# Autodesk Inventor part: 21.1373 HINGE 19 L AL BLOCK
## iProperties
Created: 2007-01
Part Number: 21.1373 HINGE 19 L AL BLOCK
Document SubType Name: Modeling
Designer: Andy Moles
Material: Aluminum-6061
Density: 2.71 g/cm^3
Mass: 18.3877 g
Surface Area: 42.4483 cm^2
Volume: 6.78512 cm^3
Author: Andy Moles
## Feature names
1. Extrusion1
2. Hole1
